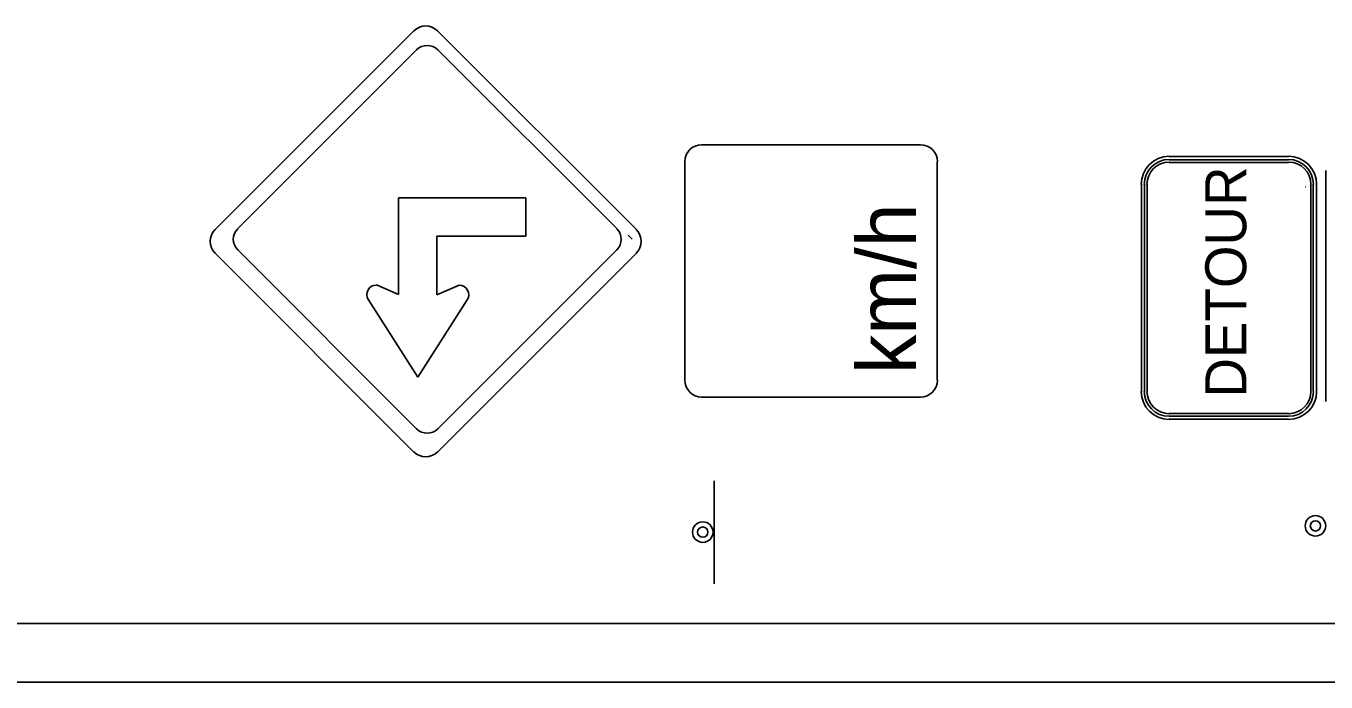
# Model space of a CAD drawing. Extents: x 1806 to 2022, y 110 to 389.
# Drawn here: x 1914.62 to 1941.53, y 225.81 to 239.4 of the extents above; entities that cross this region are included whole.
import ezdxf

# ---------------------------------------------------------------- set-up
doc = ezdxf.new("R2010")
doc.units = 0
for name, color, linetype in [('Level 10', 7, 'Continuous'), ('Level 2', 7, 'Continuous'), ('Level 44', 7, 'Continuous')]:
    doc.layers.add(name, color=color, linetype=linetype)

msp = doc.modelspace()

# ---------------------------------------------------------------- linework, layer by layer
at = {"layer": 'Level 10'}
for p, q in [((1957.331, 227.026), (1895.86, 227.026)), ((1957.331, 225.815), (1895.86, 225.815))]:
    msp.add_line(p, q, dxfattribs=at)
at = {"layer": 'Level 2'}
for p, q in [((1941.532, 231.624), (1941.532, 236.409)), ((1941.532, 231.624), (1941.532, 236.409)), ((1927.089, 235.066), (1927.167, 234.988))]:
    msp.add_line(p, q, dxfattribs=at)
at = {"layer": 'Level 44'}
for p, q in [((1922.651, 239.298), (1918.537, 235.184)), ((1927.257, 235.184), (1923.139, 239.298)), ((1919.003, 235.204), (1922.706, 238.907)), ((1923.146, 238.907), (1926.851, 235.204)), ((1928.607, 236.943), (1933.137, 236.943)), ((1928.258, 232.065), (1928.258, 236.593)), ((1933.486, 236.593), (1933.486, 232.065)), ((1938.288, 236.696), (1940.753, 236.696)), ((1938.288, 236.631), (1940.753, 236.631)), ((1938.288, 236.577), (1940.753, 236.577)), ((1938.288, 236.577), (1940.753, 236.577)), ((1938.288, 236.577), (1940.753, 236.577)), ((1937.713, 231.834), (1937.713, 236.125)), ((1937.778, 231.834), (1937.778, 236.125)), ((1937.832, 231.834), (1937.832, 236.125)), ((1937.832, 231.834), (1937.832, 236.125)), ((1937.832, 231.834), (1937.832, 236.125)), ((1941.112, 236.068), (1941.11, 236.072)), ((1941.17, 236.097), (1941.168, 236.101)), ((1941.216, 236.125), (1941.216, 231.834)), ((1941.216, 236.125), (1941.216, 231.834)), ((1941.216, 236.125), (1941.216, 231.834)), ((1941.218, 236.121), (1941.216, 236.125)), ((1941.27, 236.125), (1941.27, 231.834)), ((1941.335, 236.125), (1941.335, 231.834)), ((1924.968, 235.842), (1922.333, 235.842)), ((1922.333, 235.842), (1922.333, 233.837)), ((1924.968, 235.051), (1924.968, 235.842)), ((1923.124, 233.834), (1923.124, 235.051)), ((1923.124, 235.051), (1924.968, 235.051)), ((1918.537, 234.698), (1922.651, 230.577)), ((1922.706, 231.058), (1919.003, 234.766)), ((1923.139, 230.577), (1927.257, 234.698)), ((1926.851, 234.766), (1923.146, 231.058)), ((1941.222, 234.2), (1941.222, 234.2)), ((1941.222, 234.2), (1941.222, 234.2)), ((1941.222, 234.2), (1941.222, 234.2)), ((1922.333, 233.837), (1921.875, 234.038)), ((1923.587, 234.032), (1923.124, 233.834)), ((1921.708, 233.733), (1922.733, 232.125)), ((1922.733, 232.125), (1923.755, 233.73)), ((1933.137, 231.715), (1928.607, 231.715)), ((1933.138, 231.715), (1933.137, 231.715)), ((1933.486, 231.715), (1933.486, 231.715)), ((1940.753, 231.378), (1938.288, 231.378)), ((1940.753, 231.378), (1938.288, 231.378)), ((1940.753, 231.378), (1938.288, 231.378)), ((1940.753, 231.324), (1938.288, 231.324)), ((1940.753, 231.259), (1938.288, 231.259)), ((1923.139, 230.581), (1923.139, 230.577)), ((1922.891, 230.331), (1922.891, 230.331)), ((1928.869, 227.848), (1928.869, 229.981))]:
    msp.add_line(p, q, dxfattribs=at)
for centre, radius in [((1928.63, 228.919), 0.213), ((1928.63, 228.919), 0.107), ((1941.314, 229.049), 0.213), ((1941.314, 229.049), 0.107)]:
    msp.add_circle(centre, radius, dxfattribs=at)
for centre, radius, start, end in [((1922.895, 239.057), 0.345, 45, 135), ((1922.926, 238.689), 0.31, 45, 135), ((1928.609, 236.594), 0.349, 90, 180), ((1933.138, 236.594), 0.349, 360, 90), ((1938.287, 236.121), 0.581, 90, 180), ((1938.287, 236.121), 0.516, 90, 180), ((1938.287, 236.121), 0.462, 90, 180), ((1938.287, 236.121), 0.462, 90, 180), ((1938.287, 236.121), 0.462, 90, 180), ((1940.757, 236.121), 0.581, 0, 90), ((1940.757, 236.121), 0.516, 0, 90), ((1940.757, 236.121), 0.462, 0, 90), ((1940.757, 236.121), 0.462, 0, 90), ((1940.757, 236.121), 0.462, 0, 90), ((1918.779, 234.94), 0.345, 135, 225), ((1919.222, 234.984), 0.31, 135, 225), ((1926.631, 234.984), 0.31, 315, 45), ((1927.011, 234.94), 0.345, 315, 45), ((1921.875, 233.839), 0.198, 89.8942, 212.4962), ((1923.588, 233.835), 0.198, 327.5014, 89.8949), ((1928.609, 232.065), 0.349, 180, 270), ((1933.138, 232.065), 0.349, 270, 360), ((1938.287, 231.834), 0.581, 180, 270), ((1938.287, 231.834), 0.516, 180, 270), ((1938.287, 231.834), 0.462, 180, 270), ((1938.287, 231.834), 0.462, 180, 270), ((1938.287, 231.834), 0.462, 180, 270), ((1940.757, 231.834), 0.462, 270, 360), ((1940.757, 231.834), 0.462, 270, 360), ((1940.757, 231.834), 0.581, 270, 360), ((1940.757, 231.834), 0.516, 270, 360), ((1940.757, 231.834), 0.462, 270, 360), ((1922.926, 231.279), 0.31, 225, 315), ((1922.895, 230.824), 0.345, 225, 315)]:
    msp.add_arc(centre, radius, start, end, dxfattribs=at)

# ---------------------------------------------------------------- texts
for s, height, p in [('DETOUR', 0.848, (1939.882, 231.705)), ('km/h', 1.218, (1933.044, 232.195)), ('km/h', 1.218, (1933.044, 232.195))]:
    msp.add_text(s, height=height, rotation=90, dxfattribs=at).set_placement(p)

doc.saveas('drawing.dxf')
